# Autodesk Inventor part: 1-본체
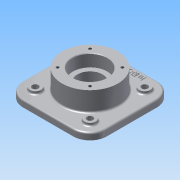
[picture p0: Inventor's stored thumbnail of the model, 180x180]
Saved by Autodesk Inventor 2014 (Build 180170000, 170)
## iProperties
Created: 2015-09
Part Number: 1-본체
Material: 알루미늄 6061
Document SubType Name: Modeling
Designer: study
Density: 2.71 g/cm^3
Appearance: 알루미늄 - 평지
Mass: 1464.68 g
Surface Area: 800.934 cm^2
Volume: 540.471 cm^3
Author: study
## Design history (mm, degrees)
sketch "스케치1"
  geometry: L1 (-75, 75)-(75, 75); L2 (75, 75)-(75, -75); L3 (75, -75)-(-75, -75); L4 (-75, -75)-(-75, 75); L5 (-75, 75)-(75, -75); L6 (75, 75)-(-75, -75); 1 further point
  constraints: 12 end point, 2 midpoint, 2 parallel, 1 horizontal, 1 perpendicular
  dimensions: "d0" = 150 distance of L1.start L1.end; "d1" = 150 distance of L1.end L2.end
extrude "돌출1" new body sketch "스케치1" distance "d2" = 12; taper "d3" = 0 deg
fillet "모깎기1" dims "d4" = 30
sketch "스케치2"
  geometry: C1 r 50 at (0, 0); 1 further point
  constraints: 1 centre point, 1 coincident
  dimensions: "d5" = 100 diameter of C1
extrude "돌출2" join sketch "스케치2" distance "d6" = 35; taper "d7" = 0 deg
sketch "스케치3"
  geometry: C1 r 50 at (0, 0) reference; 1 further point
extrude "돌출3" join sketch "스케치3" distance "d8" = 23; taper "d9" = 0 deg
hole "구멍1" diameter "d12" = 45; stored, may be unused: countersink angle "d16" = 90 deg, drill point angle "d18" = 118 deg; dims "d10" = 10, "d11" = 10, "d13" = 6, "d14" = 62, "d15" = 22, "d17" = 8
hole "구멍2" diameter "d21" = 45; stored, may be unused: countersink angle "d25" = 90 deg, drill point angle "d27" = 118 deg; dims "d19" = 10, "d20" = 10, "d22" = 6, "d23" = 62, "d24" = 22, "d26" = 8
sketch "스케치4"
  geometry: C1 r 50 at (0, 0) reference; C2 r 10 at (-49, -49); C3 r 10 at (49, -49); C4 r 10 at (49, 49); C5 r 10 at (-49, 49); C6 r 5.5 at (-49, 49); C7 r 5.5 at (-49, -49); C8 r 5.5 at (49, -49); C9 r 5.5 at (49, 49)
  constraints: 8 centre point, 4 coincident, 2 horizontal alignment, 2 vertical alignment, 1 equal radius
  dimensions: "d31" = 49 horizontal distance of C2.centre C1.centre; "d33" = 98 distance of C5.centre C4.centre; "d34" = 49 horizontal distance of C1.centre C4.centre; "d35" = 98 distance of C2.centre C5.centre; "d36" = 20 diameter of C5; "d37" = 20 diameter of C4; "d38" = 20 diameter of C2; "d41" = 11 diameter of C9; "d42" = 11 diameter of C8; "d43" = 11 diameter of C7; "d44" = 11 diameter of C6
extrude "돌출4" join sketch "스케치4" distance "d39" = 5; taper "d40" = 0 deg
extrude "돌출5" cut sketch "스케치4" stored distance "d45" = 30; taper "d46" = 0 deg
sketch "스케치5"
  geometry: L1 (-28.991, 28.991)-(28.991, 28.991); L2 (28.991, 28.991)-(28.991, -28.991); L3 (28.991, -28.991)-(-28.991, -28.991); L4 (-28.991, -28.991)-(-28.991, 28.991); L5 (-28.991, 28.991)-(28.991, -28.991); L6 (28.991, 28.991)-(-28.991, -28.991); C1 r 50 at (0, 0) reference; 4 further points
  constraints: 12 end point, 4 coincident, 2 midpoint, 2 parallel, 2 perpendicular, 1 horizontal
  dimensions: "d47" = 82 distance of L2.end L1.start
hole "구멍3" sketch "스케치5" at (-28.991, 28.991), (28.991, 28.991), (28.991, -28.991), (-28.991, -28.991) diameter "d48" = 4.917; stored, may be unused: countersink angle "d52" = 90 deg, drill point angle "d54" = 118 deg; dims "d49" = 10, "d50" = 4, "d51" = 2, "d53" = 13
node "작업 평면1"
sketch "스케치6"
  geometry: C1 r 50 at (0, 0) reference; 1 further point
  constraints: 1 vertical alignment, 1 other
  dimensions: "d55" = 65 distance of C1.centre point (0, 65)
feature "엠보싱1" sketch "스케치6" dims "d0" = 150, "d1" = 150, "d15" = 22, "d56" = 1, "d57" = 0
chamfer "모따기1" distance "d58" = 1; stored, may be unused: second distance "d59" = 2, angle "d60" = 45 deg
fillet "모깎기2" dims "d61" = 3, "d62" = 0.3, "d63" = 3
node "솔리드1"
mirror "대칭1"
